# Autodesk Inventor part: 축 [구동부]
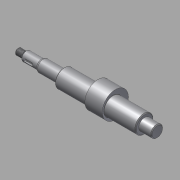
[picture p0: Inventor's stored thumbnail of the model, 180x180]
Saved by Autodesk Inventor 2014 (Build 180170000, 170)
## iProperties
Created: 2015-12
Part Number: 축 [구동부]
Document SubType Name: Modeling
Designer: mdu
Density: 1 g/cm^3
Material: 강철, 연강
Mass: 62.304 g
Surface Area: 127.382 cm^2
Volume: 62.304 cm^3
Appearance: 강철
Author: mdu
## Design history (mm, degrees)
sketch "스케치1"
  geometry: L1 (62, 100.9)-(62, 67.1) reference; L2 (51, 101.2)-(51, 84) reference; L3 (-51, 84)-(-51, 101.2) reference; L4 (-62, 67.1)-(-62, 100.9) reference; L5 (-51.6, 91.5)-(-61.4, 91.5) reference; L6 (51.6, 91.5)-(61.4, 91.5) reference; L7 (67, 84)-(-109, 84); L8 (-77, 64.201)-(-77, 103.799) reference; L9 (67, 84)-(67, 91.5); L10 (67, 91.5)-(51, 91.5); L11 (51, 91.5)-(51, 95.5); L12 (51, 95.5)-(-51, 95.5); L13 (-51, 95.5)-(-51, 91.5); L14 (-51, 91.5)-(-79, 91.5); L15 (-79, 91.5)-(-79, 90); L16 (-79, 90)-(-99, 90); L17 (-99, 90)-(-99, 87); L18 (-100.5, 88)-(-109, 88); L19 (-109, 88)-(-109, 84); L20 (-99, 87)-(-100.5, 87); L21 (-100.5, 87)-(-100.5, 88); 2 further points
  constraints: 32 end point, 7 parallel, 6 point on line, 5 perpendicular, 2 collinear, 2 horizontal, 1 midpoint, 4 other
  dimensions: "d0" = 5 distance from line of L7.start L1; "d2" = 2 distance between parallel lines of L15 L8; "d3" = 23 diameter of L12 L7; "d4" = 12 diameter of L16 L7; "d5" = 1.5 distance of L17.end L20.end; "d6" = 6 diameter of L20 L7; "d7" = 20 distance of L15.end L16.end; "d8" = 10 distance between parallel lines of L17 L19; "d9" = 8 diameter of L18 L7
revolve "회전1" sketch "스케치1" stored, may be unused: angle "d10" = 90 deg
sketch "스케치2"
  geometry: C1 r 11.5 at (84, 0) reference; C2 r 11.5 at (84, 0) reference; C3 r 16.5 at (87, 0); 1 further point
  constraints: 1 centre point, 1 horizontal alignment
  dimensions: "d11" = 33 diameter of C3; "d12" = 3 distance of C3.centre C1.centre
extrude "돌출1" join sketch "스케치2" stored distance "d13" = 22; taper "d14" = 0 deg
chamfer "모따기1" distance "d15" = 1; stored, may be unused: second distance "d16" = 2, angle "d17" = 45 deg
feature "스레드1" dims "d18" = 10, "d19" = 0
node "작업 평면1"
sketch "스케치3"
  geometry: L1 (-5, -2)-(3, -2); L2 (3, 2)-(-5, 2); L3 (-10, -5)-(-10, 5) reference; A1 r 2 centre (3, 0) between (3, -2) and (3, 2); A2 r 2 centre (-5, 0) between (-5, 2) and (-5, -2); 2 further points
  constraints: 4 end point, 4 point on circle, 4 tangent, 2 centre point, 1 horizontal, 1 horizontal alignment, 1 midpoint, 1 parallel
  dimensions: "d20" = 4 distance between parallel lines of L1 L2; "d21" = 12 dimension on A1 A2; "d22" = 3 distance edge to line of A2 L3
extrude "돌출2" cut sketch "스케치3" distance "d23" = 2.5; taper "d24" = 0 deg
fillet "모깎기1" dims "d25" = 0.3
fillet "모깎기2" dims "d26" = 3
node "솔리드1"
node "참조1"
node "참조2"
node "참조3"
node "참조4"
node "참조5"
node "투영된 루프1"
